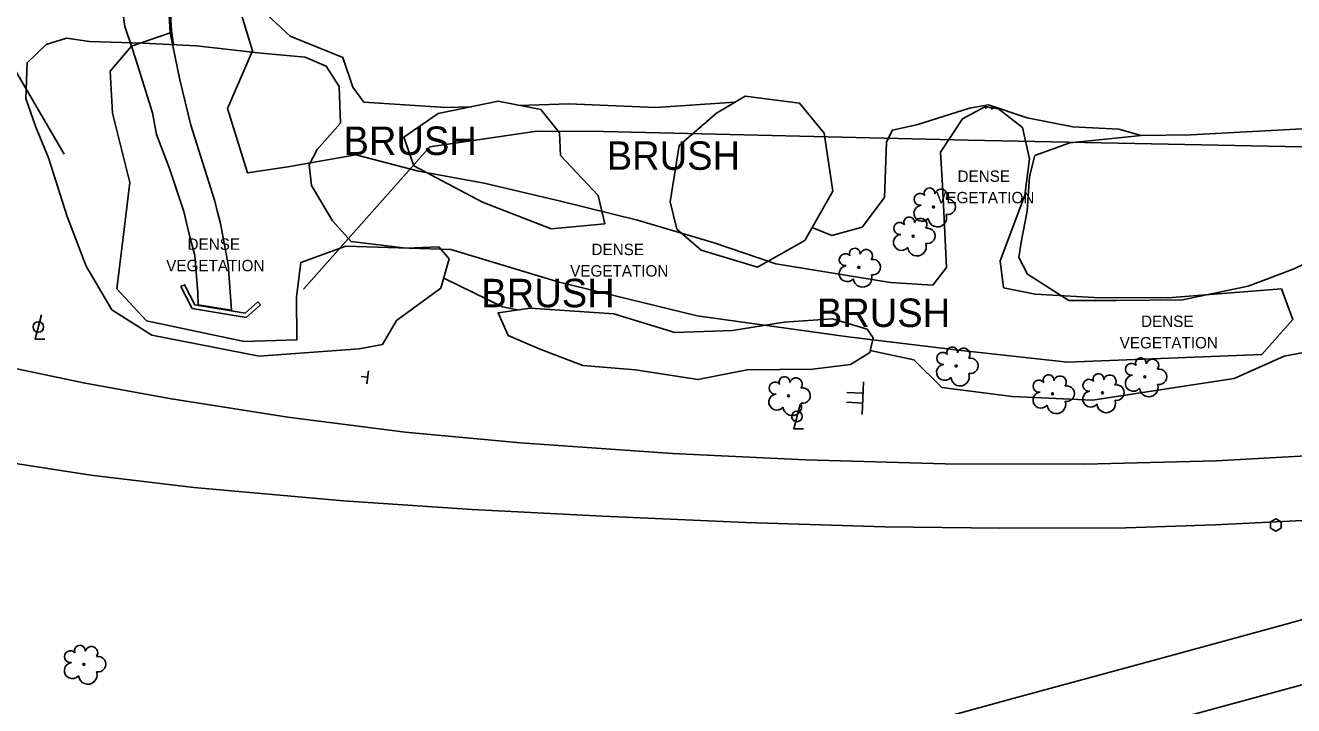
# Model space of a CAD drawing. Extents: x 2129547 to 2134906, y 657330 to 659734.
# Drawn here: x 2132793.8 to 2133105.5, y 658769 to 658936.3 of the extents above; entities that cross this region are included whole.
import ezdxf

# ---------------------------------------------------------------- set-up
doc = ezdxf.new("R2010")
doc.units = 0
for name, color, linetype in [('Default', 7, 'Continuous'), ('DR_X_Culvert', 7, 'Continuous'), ('HY_X_Water_Edge', 7, 'Continuous'), ('LT_X_Poles', 7, 'Continuous'), ('PM_X_Edge_Line', 7, 'Continuous'), ('PV_X_EOP2', 7, 'Continuous'), ('RD_X_Cells', 7, 'Continuous'), ('RD_X_Fence', 7, 'Continuous'), ('RD_X_Misc_Items', 7, 'Continuous'), ('SN_X_Public', 7, 'Continuous'), ('VG_X_Cells', 7, 'Continuous'), ('VG_X_Shrub_Line_Lt', 7, 'Continuous'), ('VG_X_Text', 7, 'Continuous'), ('VG_X_Tree_Line_Lt', 7, 'Continuous')]:
    doc.layers.add(name, color=color, linetype=linetype)

# ---------------------------------------------------------------- blocks, each defined once
blk = doc.blocks.new('CULVERT')
at = {"layer": 'Default'}
blk.add_lwpolyline([(-0.0508, 0.1143), (0, 0.0635), (0, -0.0635), (-0.0508, -0.1143)], dxfattribs=at)
blk = doc.blocks.new('LPOLE')
at = {"layer": 'LT_X_Poles'}
blk.add_lwpolyline([(0.01, 0.0375), (-0.01, -0.0385), (0.02, -0.0385)], dxfattribs=at)
blk.add_circle((0, 0), 0.0165, dxfattribs=at)
blk = doc.blocks.new('POST')
at = {"layer": 'RD_X_Cells'}
blk.add_lwpolyline([(-0.0165, -0.0095), (0, -0.019), (0.0165, -0.0095), (0.0165, 0.0095), (0, 0.019), (-0.0165, 0.0095), (-0.0165, -0.0095)], dxfattribs=at)
blk = doc.blocks.new('SGN1P')
at = {"layer": 'SN_X_Public'}
for p, q in [((0, 0), (-0.02032, 0)), ((0, 0.02032), (0, -0.02032))]:
    blk.add_line(p, q, dxfattribs=at)
blk = doc.blocks.new('POINT_DISPLAY')
at = {"layer": 'Default'}
blk.add_line((0, 0), (0, 0), dxfattribs=at)
blk = doc.blocks.new('SGN2P')
at = {"layer": 'Default'}
for p, q in [((0, 0.0203), (0, -0.0203)), ((0, 0.0061), (-0.0203, 0.0061)), ((0, -0.0061), (-0.0203, -0.0061))]:
    blk.add_line(p, q, dxfattribs=at)
blk.add_blockref('POINT_DISPLAY', (0, 0), dxfattribs=at)
blk = doc.blocks.new('TREE')
at = {"layer": 'VG_X_Cells'}
blk.add_circle((0, 0), 0.00305, dxfattribs=at)
for centre, radius, start, end in [((-0.042, 0.0237), 0.0187, 39.0625, 279.5412), ((-0.0125, 0.0428), 0.0167, 354.0047, 205.9741), ((0.0232, 0.0359), 0.0197, 323.83, 165.0376), ((-0.0362, -0.0197), 0.0251, 96.1722, 320.5737), ((0.0439, 0.0005), 0.0243, 259.1453, 101.4596), ((0.012, -0.0331), 0.029, 184.9476, 19.4572)]:
    blk.add_arc(centre, radius, start, end, dxfattribs=at)

msp = doc.modelspace()

# ---------------------------------------------------------------- linework, layer by layer
at = {"layer": 'DR_X_Culvert'}
msp.add_lwpolyline([(2132832.08, 658872.07), (2132834.82, 658866.7), (2132848.13, 658864.49), (2132851.63, 658867.55), (2132850.97, 658868.3), (2132847.83, 658865.56), (2132835.48, 658867.6), (2132832.97, 658872.52)], close=True, dxfattribs=at)
at = {"layer": 'HY_X_Water_Edge'}
for points in [[(2132839.86, 658867), (2132836.34, 658867.58), (2132836.22, 658870.49), (2132835.5, 658879.69), (2132834.12, 658884.97), (2132832.8, 658890.55), (2132829.28, 658901.08), (2132826.09, 658909.43), (2132825.08, 658914.78), (2132821.02, 658927.88), (2132819.9, 658931.19), (2132818.26, 658936.03), (2132816.8, 658946.57), (2132816.15, 658964.85), (2132815.59, 658980.83)], [(2132839.86, 658867), (2132844.49, 658866.25), (2132843.65, 658877.53), (2132841.8, 658887.6), (2132841, 658890.66), (2132840.38, 658893.05), (2132834.49, 658911.74), (2132831.84, 658922.87), (2132829.47, 658934.44), (2132828.65, 658948.92), (2132834.85, 658972.67)]]:
    msp.add_lwpolyline(points, dxfattribs=at)
at = {"layer": 'PM_X_Edge_Line'}
for points in [[(2133329.04, 658861.1), (2133300.92, 658854.17), (2133274.71, 658848.24), (2133248.43, 658843.47), (2133232.93, 658841.23), (2133211.46, 658838.73), (2133186.01, 658836.22), (2133155.02, 658833.66), (2133121.79, 658831.17), (2133086.55, 658829.19), (2133054.09, 658828.41), (2133019.86, 658828.5), (2132985.53, 658829.46), (2132952.85, 658830.98), (2132915.52, 658833.61), (2132887.18, 658836.26), (2132858.31, 658839.93), (2132829.74, 658844.45), (2132808.54, 658848.31), (2132773.75, 658855.57)], [(2133352.86, 658840.89), (2133312.19, 658829.94), (2133247.7, 658812.58), (2133183.7, 658795.08), (2133146.25, 658784.96), (2133107.51, 658774.1), (2133073.85, 658764.93), (2133041.79, 658756.19), (2133011.05, 658747.8), (2132979.94, 658739.33), (2132948.72, 658730.94), (2132917.57, 658722.29), (2132887.16, 658713.87), (2132857, 658705.5), (2132818.68, 658695.21), (2132780.46, 658684.71), (2132740.98, 658673.64), (2132705.56, 658663.7), (2132666.4, 658652.81), (2132631.49, 658643.36), (2132595.52, 658633.47), (2132567.08, 658625.72), (2132529.28, 658615.18)], [(2133006.99, 658762.7), (2133037.72, 658771.1), (2133069.79, 658779.83), (2133103.39, 658788.99), (2133142.1, 658799.84), (2133179.64, 658810.26), (2133239.99, 658826.51), (2133196.39, 658821.58), (2133169.12, 658819.19), (2133139.39, 658816.63), (2133112.72, 658814.83), (2133086.2, 658813.46), (2133064.26, 658812.76), (2133033.29, 658812.66), (2133005.07, 658813.03), (2132970.88, 658814.09), (2132935.7, 658815.58), (2132903.64, 658817.26), (2132872, 658819.38), (2132835.28, 658822.67), (2132809.95, 658825.67), (2132783.95, 658829.71)]]:
    msp.add_lwpolyline(points, dxfattribs=at)
at = {"layer": 'PV_X_EOP2'}
for points in [[(2133352.86, 658840.89), (2133312.19, 658829.94), (2133247.7, 658812.58), (2133183.7, 658795.08), (2133146.25, 658784.96), (2133107.51, 658774.1), (2133073.85, 658764.93), (2133041.79, 658756.19), (2133011.05, 658747.8), (2132979.94, 658739.33), (2132948.72, 658730.94), (2132917.57, 658722.29), (2132887.16, 658713.87), (2132857, 658705.5), (2132818.68, 658695.21), (2132780.46, 658684.71), (2132740.98, 658673.64), (2132705.56, 658663.7), (2132666.4, 658652.81), (2132631.49, 658643.36), (2132595.52, 658633.47), (2132567.08, 658625.72), (2132529.28, 658615.18)], [(2132529.63, 658631.32), (2132552.22, 658637.55), (2132563.39, 658640.65), (2132591.42, 658648.37), (2132627.43, 658658.26), (2132662.31, 658667.71), (2132701.4, 658678.58), (2132736.81, 658688.52), (2132776.33, 658699.59), (2132814.63, 658710.12), (2132852.93, 658720.4), (2132883.03, 658728.76), (2132913.44, 658737.18), (2132944.65, 658745.84), (2132975.91, 658754.24), (2133006.99, 658762.7), (2133037.72, 658771.1), (2133069.79, 658779.83), (2133103.39, 658788.99), (2133142.1, 658799.84), (2133179.64, 658810.26), (2133239.99, 658826.51)]]:
    msp.add_lwpolyline(points, dxfattribs=at)
at = {"layer": 'RD_X_Fence'}
for points in [[(2132570.32, 659011.47), (2132632.1, 658988.26), (2132739.36, 658948.59), (2132788.43, 658930.38), (2132803.36, 658904.61)], [(2132862.2, 658871.41), (2132893.21, 658906.4), (2132919.58, 658910.31), (2132935.95, 658910.2), (2133025.5, 658908.09), (2133173.05, 658905.09), (2133177.13, 658884.47), (2133277.21, 658906.58), (2133331.89, 658921.65)]]:
    msp.add_lwpolyline(points, dxfattribs=at)
at = {"layer": 'RD_X_Misc_Items'}
msp.add_lwpolyline([(2132828.65, 658948.92), (2132829.47, 658934.44), (2132819.9, 658931.19), (2132818.45, 658929.47), (2132814.66, 658925.01), (2132815.27, 658914.73), (2132819.52, 658897.66), (2132817.89, 658884.1), (2132816.34, 658871.53), (2132823.6, 658863.66), (2132847.63, 658858.57), (2132860.57, 658858.99), (2132860.44, 658869.51), (2132861.53, 658877.96), (2132872.59, 658881.98), (2132898.43, 658881.22), (2132925.04, 658873.17), (2132958.98, 658864.87), (2132996.08, 658859.67), (2133023.14, 658856.39), (2133049.97, 658853.46), (2133097.67, 658855.36), (2133105.36, 658864), (2133102.51, 658871.5), (2133074.59, 658869.33), (2133056.53, 658869.4), (2133041.98, 658870.17), (2133034.25, 658871.77), (2133033.37, 658878.4), (2133039.43, 658894.56), (2133040.62, 658903.5), (2133038.91, 658911.17), (2133033.01, 658915.76), (2133029.79, 658916.34), (2133024.11, 658913.32), (2133018.75, 658905.12), (2133019.33, 658895.51), (2133020.18, 658876.78), (2133016.82, 658872.45), (2133006.44, 658873.09), (2132978.24, 658877.69), (2132963.12, 658882.78), (2132944.25, 658888.37), (2132925.38, 658893.07), (2132906.57, 658897.53), (2132890.42, 658900.46), (2132875.02, 658904.45), (2132858.38, 658901.48), (2132848.4, 658900.03), (2132843.55, 658915.84), (2132849.67, 658930.01), (2132845.25, 658944.59)], dxfattribs=at)
at = {"layer": 'VG_X_Shrub_Line_Lt'}
for points in [[(2132830.28, 658931.55), (2132829.79, 658934.95), (2132829.01, 658947.32), (2132826.44, 658955.9), (2132817.88, 658967.72), (2132819.67, 658987.42), (2132831.4, 658986.17), (2132834.64, 658983.32), (2132833.71, 658960.55), (2132846.18, 658957.11), (2132849.7, 658959.04), (2132853, 658954.46), (2132850.83, 658950.16), (2132850.88, 658941.13), (2132858.92, 658933.66), (2132871.87, 658928.41), (2132874.34, 658921.11), (2132877.03, 658917.44), (2132897.21, 658916.11), (2132903.49, 658916.29)], [(2132915.35, 658916.62), (2132927.36, 658916.96), (2132948.81, 658916.09), (2132968.23, 658917.43)], [(2132987.18, 658886.58), (2132992.01, 658884.6), (2132999.45, 658886.71), (2133004.98, 658893.97), (2133005.47, 658907.68), (2133006.93, 658910.55), (2133013.15, 658911.9), (2133025.85, 658915.93), (2133030.51, 658916.73), (2133040, 658913.52), (2133051.23, 658911.36), (2133062.57, 658910.78), (2133068.08, 658909.18)], [(2132914.78, 658866.31), (2132911.11, 658867.05), (2132896.66, 658874.13)], [(2133196.68, 658860.72), (2133168.23, 658856.99), (2133134.64, 658860.95), (2133103.19, 658854.92), (2133090.89, 658849.45), (2133056.09, 658844.17), (2133036.34, 658845.04), (2133019.09, 658847.25), (2133012.2, 658854.08), (2133001.46, 658856.33)]]:
    msp.add_lwpolyline(points, dxfattribs=at)
at = {"layer": 'VG_X_Tree_Line_Lt'}
for points in [[(2132875.87, 658856.72), (2132851.33, 658854.95), (2132824.9, 658860.08), (2132815.06, 658866.36), (2132808.75, 658877.06), (2132804.1, 658889.3), (2132799.56, 658903.68), (2132796.45, 658911.22), (2132793.97, 658918.3), (2132794.25, 658927.08), (2132798.95, 658931.56), (2132803.96, 658933.12), (2132809.61, 658932.31), (2132822.7, 658931.91), (2132835.94, 658931.28), (2132851.8, 658929.45), (2132862.63, 658928.45), (2132867.78, 658926.23), (2132870.99, 658921.22), (2132871.3, 658912.23), (2132865.56, 658905.75), (2132863.57, 658902.02), (2132864.14, 658896.93), (2132869.35, 658888.21), (2132873.89, 658883.12), (2132887.43, 658881.5), (2132895.45, 658881.82), (2132898.01, 658878.89), (2132895.97, 658871.68), (2132885.07, 658863.74), (2132881.61, 658857.84)], [(2132952.34, 658892.92), (2132954.52, 658906.76), (2132963.66, 658914.7), (2132970.73, 658918.92), (2132984.11, 658917.19), (2132990.13, 658909.79), (2132992.27, 658895.51), (2132985.39, 658883.43), (2132973.78, 658876.85), (2132959.94, 658881.02), (2132953.98, 658886.22)], [(2132925.32, 658904.27), (2132934.58, 658894.42), (2132936.26, 658887.53), (2132923.06, 658886.25), (2132906.15, 658892.85), (2132889.35, 658901.72), (2132886.83, 658908.78), (2132895.29, 658914.61), (2132910.07, 658917.63), (2132920.55, 658915.62), (2132925.11, 658909.89)], [(2132987.31, 658851.78), (2132971.2, 658851.61), (2132959.11, 658849.21), (2132943.75, 658851.57), (2132930.87, 658852.66), (2132920.1, 658856.76), (2132912.52, 658860.02), (2132910.01, 658865.61), (2132917.91, 658866.77), (2132938.48, 658865.4), (2132953.43, 658860.76), (2132967.66, 658861.3), (2132980.36, 658863.34), (2132992.16, 658864.12), (2133000.71, 658861.63), (2133002.17, 658859.45), (2133001.35, 658855.82), (2132996.66, 658852.92)]]:
    msp.add_lwpolyline(points, close=True, dxfattribs=at)
for points in [[(2133080.22, 658909.41), (2133113.68, 658911.18), (2133134.92, 658909.9), (2133155.09, 658904.95), (2133176.83, 658906.04), (2133189.62, 658908.97), (2133201.92, 658914.47), (2133214.48, 658919.01), (2133233.98, 658923.59)], [(2133110.37, 658878.66), (2133105.38, 658876.33), (2133094.31, 658872.18), (2133078.21, 658868.79), (2133061.9, 658868.61), (2133050.25, 658868.65), (2133040.1, 658875.1), (2133038.01, 658879.18), (2133038.58, 658882.99), (2133040.06, 658890.61), (2133040.62, 658899.12), (2133041.93, 658904.27), (2133050.53, 658907.39), (2133068.08, 658909.18), (2133080.22, 658909.41)]]:
    msp.add_lwpolyline(points, dxfattribs=at)

# ---------------------------------------------------------------- block references
at = {"layer": 'DR_X_Culvert', "xscale": 7.873999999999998, "yscale": 7.8740000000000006, "rotation": 82.8097304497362}
msp.add_blockref('CULVERT', (2133030.66, 658916.11), dxfattribs=at)
at = {"layer": 'LT_X_Poles', "xscale": 78.74000000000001, "yscale": 78.74000000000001}
for p in [(2132797.04, 658862.13), (2132983.46, 658840.14)]:
    msp.add_blockref('LPOLE', p, dxfattribs=at)
at = {"layer": 'RD_X_Cells', "xscale": 78.74000000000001, "yscale": 78.74000000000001}
msp.add_blockref('POST', (2133101.14, 658813.45), dxfattribs=at)
at = {"layer": 'SN_X_Public'}
for name, p, xscale, yscale, rotation in [('SGN1P', (2132877.97, 658849.78), 78.74000000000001, 78.74000000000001, -6.501060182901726), ('SGN2P', (2132999.68, 658844.63), 196.85000000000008, 196.85000000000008, -2.4731420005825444)]:
    msp.add_blockref(name, p, dxfattribs=dict(at, xscale=xscale, yscale=yscale, rotation=rotation))
at = {"layer": 'VG_X_Cells', "xscale": 78.74000000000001, "yscale": 78.74000000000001}
for p in [(2133017.03, 658891.63), (2133012.02, 658884.48), (2132998.65, 658876.8), (2133022.6, 658852.53), (2133068.98, 658849.85), (2133046.28, 658845.7), (2133058.53, 658845.94), (2132981.38, 658845.23), (2132808.24, 658779.18)]:
    msp.add_blockref('TREE', p, dxfattribs=at)

# ---------------------------------------------------------------- texts
at = {"layer": 'VG_X_Text'}
for s, height, p in [('BRUSH', 7, (2132872.03, 658904.42)), ('BRUSH', 7, (2132936.72, 658900.77)), ('DENSE', 2.8, (2133022.93, 658897.81)), ('VEGETATION', 2.8, (2133017.68, 658892.54)), ('DENSE', 2.8, (2132833.71, 658881.1)), ('DENSE', 2.8, (2132932.98, 658879.8)), ('VEGETATION', 2.8, (2132828.46, 658875.83)), ('VEGETATION', 2.8, (2132927.73, 658874.53)), ('BRUSH', 7, (2132905.91, 658866.97)), ('BRUSH', 7, (2132988.35, 658862.13)), ('DENSE', 2.8, (2133068.02, 658862.13)), ('VEGETATION', 2.8, (2133062.78, 658856.86))]:
    msp.add_text(s, height=height, dxfattribs=at).set_placement(p)

doc.saveas('drawing.dxf')
